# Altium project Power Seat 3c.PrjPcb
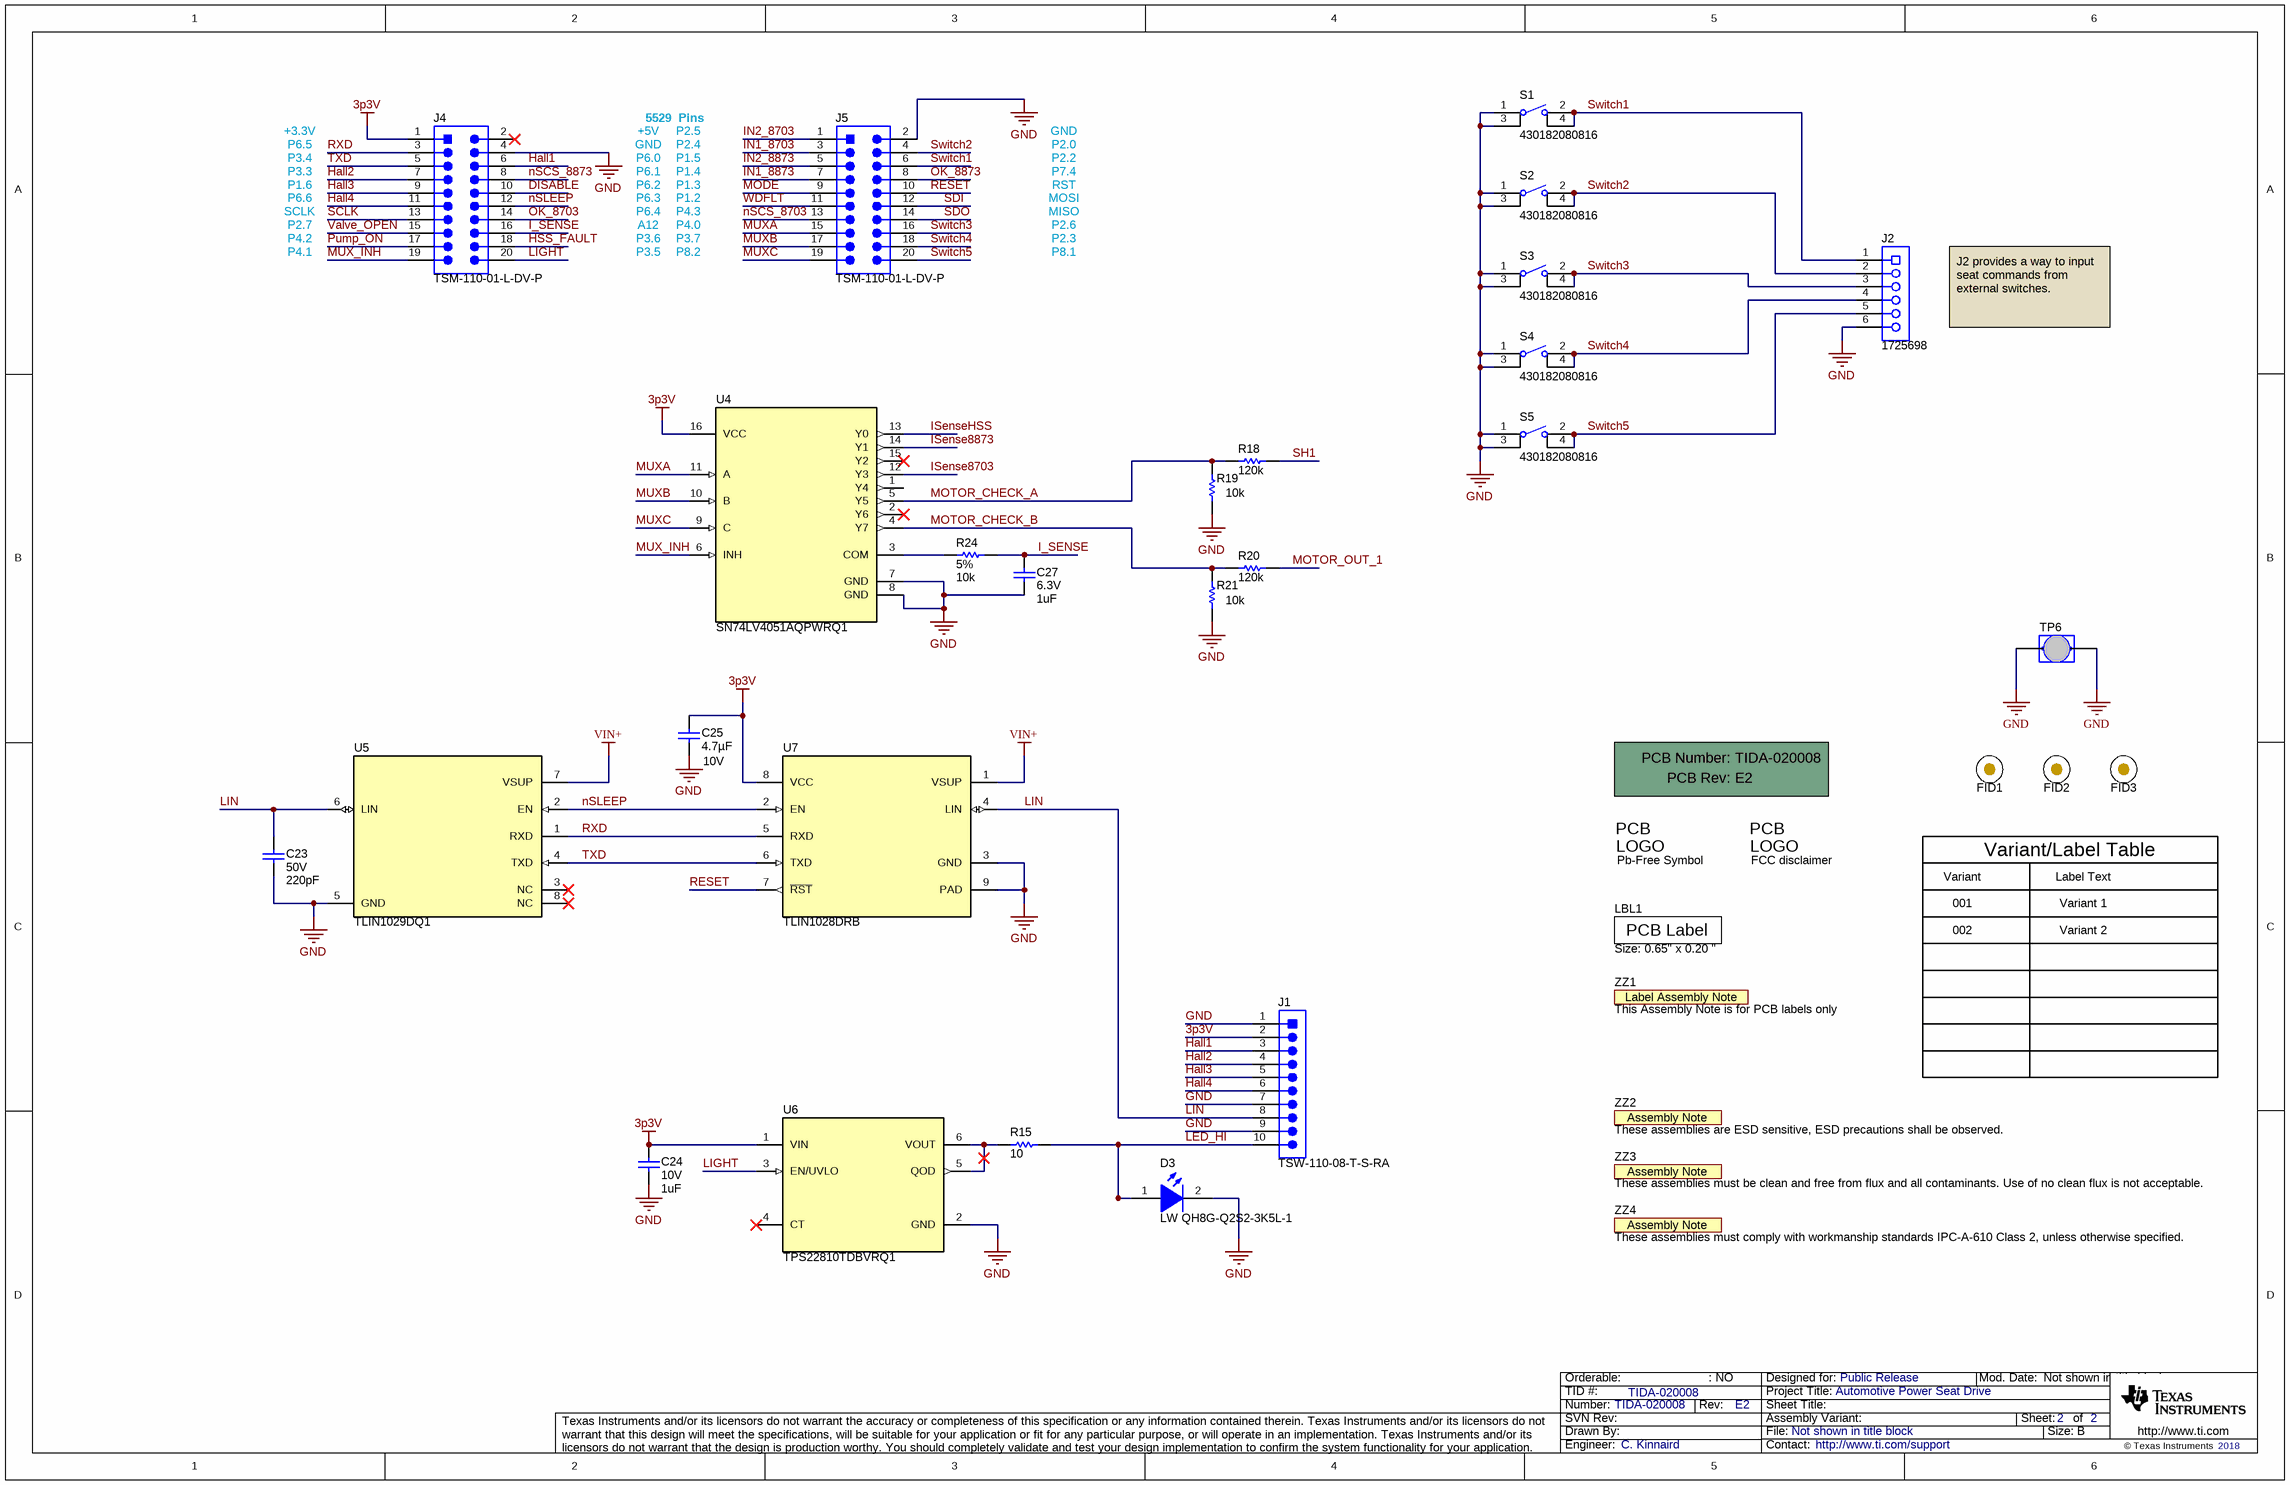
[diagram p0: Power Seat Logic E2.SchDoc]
TID: TIDA-020008; TechSupport: http://www.ti.com/support; SCH_Rev: E2; PRJ_Title: Automotive Power Seat Drive; PRJ_Number: TIDA-020008; PRJ_Engineer: C. Kinnaird; PRJ_Customer: Public Release; PCB_Rev: E2; PCB_Layout: Who did the Layout?; CopyrightYear: 2018
2 sheets, 99 parts. Net scope: global (net labels, ports and power ports of the same name join across sheets).
Board file: Power Seat E2.PcbDoc
Sheets:
  Power Seat Logic E2.SchDoc
  Power Seat Motor Drives E2.SchDoc

## Sheet Power Seat Logic E2.SchDoc
size 431 x 279 mm; Date: Not shown in title block; ApprovedBy: Not shown in title block; CheckedBy: Not shown in title block; Author: Not shown in title block; CompanyName: Not shown in title block; Engineer: Not shown in title block; Organization: Not shown in title block; Address1: Not shown in title block; Address2: Not shown in title block; Address3: Not shown in title block; Address4: Not shown in title block; DocumentNumber: 1; Revision: Use project parameter SCH_Rev; SheetNumber: 2; SheetTotal: 2; PageSetup: Record=PageOptions¦CenterHorizontal=True¦CenterVertical=True¦PrintScale=1.00¦XCorrection=1.00¦YCorrection=1.00¦PrintKind=0¦BorderSize=5000000¦LeftOffset=0¦BottomOffset=0¦Orientation=2¦PaperLength=1000¦PaperWidth=1000¦Scale=100¦PaperSource=15¦PrintQuality=600¦MediaType=1¦DitherType=10¦PaperKind=Letter¦PrintScaleMode=1

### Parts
!PCB1  Printed Circuit Board  (value not drawn)  (mechanical)
C23  VDC_V: 50V  ValueDisplayed: 220pF  [0805_HV]  (hidden comment: C0805C221K5RACTU)
C24  VDC_V: 10V  ValueDisplayed: 1uF  [0603]  (hidden comment: LMK107B7105KAHT)
C25  ValueDisplayed: 4.7µF  Value2: 10V  [0805_HV]  (hidden comment: C2012X7R1A475M125AC)
C27  VDC_V: 6.3V  ValueDisplayed: 1uF  [0402]  (hidden comment: GRM155R70J105MA12D)
D3  LW QH8G-Q2S2-3K5L-1  [LW QH8G_White]
FID1  Fiducial  [Fiducial10-20]  (value not drawn)
FID2  Fiducial  [Fiducial10-20]  (value not drawn)
FID3  Fiducial  [Fiducial10-20]  (value not drawn)
J1  TSW-110-08-T-S-RA  [Samtec_TSW-110-08-x-S-RA]
J2  1725698  [Phoenix_1725698]
J4  TSM-110-01-L-DV-P  [CONN_TSM-110-01-T-DV-P]
J5  TSM-110-01-L-DV-P  [CONN_TSM-110-01-T-DV-P]
LBL1  Size: 0.65" x 0.20 "  [Label_650x200]
Logo2  Pb-Free Symbol  [Pb-Free_Overlay_Small]  (no BOM)
Logo3  FCC disclaimer  [FCC_disclaimer]  (no BOM)
R15  ValueDisplayed: 10  [0603]  (hidden comment: CRCW060310R0JNEAHP)
R18  ValueDisplayed: 120k  [0402]  (hidden comment: CRCW0402120KJNED)
R19  ValueDisplayed: 10k  [0402]  (hidden comment: CRCW040210K0JNED)
R20  ValueDisplayed: 120k  [0402]  (hidden comment: CRCW0402120KJNED)
R21  ValueDisplayed: 10k  [0402]  (hidden comment: CRCW040210K0JNED)
R24  Value1: 5%  ValueDisplayed: 10k  [0402]  (hidden comment: CRCW040210K0JNED)
S1  430182080816  [SW_430182080816]
S2  430182080816  [SW_430182080816]
S3  430182080816  [SW_430182080816]
S4  430182080816  [SW_430182080816]
S5  430182080816  [SW_430182080816]
TP6  D3082-05  [Harwin_D3082-05]  (value not drawn)
U4  SN74LV4051AQPWRQ1  [PW0016A_N]
U5  TLIN1029DQ1  [D0008A_N]
U6  PartNumber: TPS22810TDBVRQ1  [DBV0006A_N]  (hidden comment: TPS22810DBVR)
U7  TLIN1028DRB  [DRB0008F]
ZZ1  This Assembly Note is for PCB labels only  [AssemblyNoteLabel]  (no BOM)
ZZ2  These assemblies are ESD sensitive, ESD precautions shall be observed.  [AssemblyNote]  (no BOM)
ZZ3  These assemblies must be clean and free from flux and all contaminants. Use of no clean flux is not acceptable.  [AssemblyNote]  (no BOM)
ZZ4  These assemblies must comply with workmanship standards IPC-A-610 Class 2, unless otherwise specified.  [AssemblyNote]  (no BOM)

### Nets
3p3V: C24.1 C25.1 J1.2 J4.1 U4.16(VCC) U6.1(VIN) U7.8(VCC)
GND: C23.1 C24.2 C25.2 C27.2 D3.2(K) J1.1 J1.7 J1.9 J2.6 J4.4 J5.2 R19.1 R21.1 S1.1 S1.3 S2.1 S2.3 S3.1 S3.3 S4.1 S4.3 S5.1 S5.3 TP6.1 TP6.2 U4.7(GND) U4.8(GND) U5.5(GND) U6.2(GND) U7.3(GND) U7.9(PAD)
VIN+: U5.7(VSUP) U7.1(VSUP)
DISABLE: J4.10
Hall1: J1.3 J4.6
Hall2: J1.4 J4.7
Hall3: J1.5 J4.9
Hall4: J1.6 J4.11
HSS_FAULT: J4.18
I_SENSE: C27.1 J4.16 R24.1
IN1_8703: J5.3
IN1_8873: J5.7
IN2_8703: J5.1
IN2_8873: J5.5
ISense8703: U4.12(Y3)
ISense8873: U4.14(Y1)
ISenseHSS: U4.13(Y0)
LED_HI: D3.1(A) J1.10 R15.2
LIGHT: J4.20 U6.3(EN/UVLO)
LIN: C23.2 J1.8 U5.6(LIN) U7.4(LIN)
MODE: J5.9
MOTOR_CHECK_A: R18.1 R19.2 U4.5(Y5)
MOTOR_CHECK_B: R20.1 R21.2 U4.4(Y7)
MOTOR_OUT_1: R20.2
MUX_INH: J4.19 U4.6(INH)
MUXA: J5.15 U4.11(A)
MUXB: J5.17 U4.10(B)
MUXC: J5.19 U4.9(C)
nSCS_8703: J5.13
nSCS_8873: J4.8
nSLEEP: J4.12 U5.2(EN) U7.2(EN)
OK_8703: J4.14
OK_8873: J5.8
Pump_ON: J4.17
RESET: J5.10 U7.7(~{RST})
RXD: J4.3 U5.1(RXD) U7.5(RXD)
SCLK: J4.13
SDI: J5.12
SDO: J5.14
SH1: R18.2
Switch1: J2.1 J5.6 S1.2 S1.4
Switch2: J2.2 J5.4 S2.2 S2.4
Switch3: J2.3 J5.16 S3.2 S3.4
Switch4: J2.4 J5.18 S4.2 S4.4
Switch5: J2.5 J5.20 S5.2 S5.4
TXD: J4.5 U5.4(TXD) U7.6(TXD)
Valve_OPEN: J4.15
WDFLT: J5.11
NetR15_1: R15.1 U6.5(QOD) U6.6(VOUT)
NetR24_2: R24.2 U4.3(COM)

Not connected (* = marked no-connect by the designer): J4 2*; U4 1(Y4) 2(Y6)* 15(Y2)*; U5 3(NC)* 8(NC)*; U6 4(CT)*

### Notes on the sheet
- +3.3V
- P6.5
- P3.4
- +5V
- GND
- P6.0
- 5529  Pins
- P2.5
- P2.4
- P1.5
- P2.0
- P2.2
- P3.3
- P1.6
- P6.6
- SCLK
- P2.7
- P6.1
- P6.2
- P6.3
- P6.4
- A12
- P1.4
- P1.3
- P1.2
- P4.3
- P4.0
- P7.4
- RST
- MOSI
- MISO
- P2.6
- P4.2
- P4.1
- P3.6
- P3.5
- P3.7
- P8.2
- P2.3
- P8.1
- J2 provides a way to input seat commands from external switches.
- Variant
- 001
- Variant/Label Table
- Label Text
- Variant 1
- 002
- Variant 2
- : NO

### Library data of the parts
!PCB1 = PCB: Manufacturer: Any; PartNumber: TIDA-020008; SymbolCreator: a0412235
C23 = CMP-0007764-2: CAP, CERM, 220 pF, 50 V, +/- 10%, X7R, 0805; Manufacturer: Kemet; TaMin_C: -55°C; ESR_ohm: 1.414; Polarized: N; SizeAreaWB_mm2: 6.75; Value1: 1.414 ohm; U/M: EA; Value: 220pF; TaMax_C: 125°C; SizeZ_mm: 1.45; SizeX_mm: 2; SizeY_mm: 1.25; Cap_Case: 0805; SizeArea_mm2: 2.5; IRMS_A: 1.11dA; AEC Category: Q200
C24 = CMP-0007505-4: CAP, CERM, 1 uF, 10 V, +/- 10%, X7R, AEC-Q200 Grade 1, 0603; Manufacturer: Taiyo Yuden; TaMin_C: -55°C; Polarized: N; SizeAreaWB_mm2: 4.68; Value1: Unknown; U/M: EA; Value: 1uF; TaMax_C: 125°C; SizeZ_mm: 1; SizeX_mm: 1.6; SizeY_mm: 0.8; SizeArea_mm2: 1.28; AEC Qualified: Y; Cap_F: 1µF; AEC Category: Q200
C25 = C2012X7R1A475M125AC: CAP, CERM, 4.7 µF, 10 V,+/- 20%, X7R, 0805; Manufacturer: TDK; Polarized: N; CompType: Capacitor; Value: 4.7uF; U/M: EA; Cap_F: 0.0000047; Tolerance_%: 20; VDC_V: 10; TaMin_C: -55; TaMax_C: 125; Cap_Case: 0805; SizeArea_mm2: 2.5; SizeAreaWB_mm2: 6.75; SizeX_mm: 2; SizeY_mm: 1.25; SizeZ_mm: 1.45; AEC Category: Q200; Green_Lifecycle: Active; Green_REACh: Passed
C27 = CMP-0006624-2: CAP, CERM, 1 uF, 6.3 V, +/- 20%, X7R, 0402; Manufacturer: MuRata; TaMin_C: -55°C; Polarized: N; SizeAreaWB_mm2: 3; Value1: Unknown; U/M: EA; Value: 1uF; TaMax_C: 125°C; SizeZ_mm: 0.6; SizeX_mm: 1; SizeY_mm: 0.5; CompType: Capacitor; Cap_F: 1µF; AEC Category: Q200
D3 = CMP-0002919-1: LED, White, SMD; Manufacturer: OSRAM; Io_A: 5mA; Vr_V: 5V; Tjmax_C: 95°C; Value1: W; U/M: EA; Angle: 120; Ir_A: 10nA; Vf_V: 2.8V
FID1-FID3 = Fiducial: Fiducial mark.  There is nothing to buy or mount.; SymbolCreator: codlsc
J1 = CMP-0075666-1: Header, 2.54mm, 10x1, Tin, R/A, TH; Manufacturer: Samtec; Pitch_mm: 2.54; Gender: Male; Cert_CSA: Y; Voltage_V: 550V; CT: False; Shrouded: N; Row_Count: 1; CNHeader: True
J2 = CMP-0055512-1: Terminal Block, 6x1, 2.54mm, TH; Manufacturer: Phoenix Contact; CNHeader: FALSE; Current_A: 6A; Cert_CSA: Y; Voltage_V: 160V; Row_Count: 1; Pitch_mm: 2.54; CT: TRUE
J4 J5 = CMP-0075600-2: Header, 2.54mm, 10x2, Gold, SMT; Manufacturer: Samtec; Pitch_mm: 2.54; Gender: Male; Cert_CSA: Y; Green_REACh: Passed; Current_A: 5.4A; Voltage_V: 475V; Shrouded: N; Green_Lifecycle: Active; Row_Count: 2
LBL1 = THT-14-423-10: Thermal Transfer Printable Labels, 0.650" W x 0.200" H - 10,000 per roll; Manufacturer: Brady; SymbolCreator: a0412235; CompType: Label
Logo2 = Pb-Free: SymbolCreator: a0412235
Logo3 = FCC_disclaimer: SymbolCreator: codlsc
R15 = CMP-0025704-4: RES, 10, 5%, 0.25 W, AEC-Q200 Grade 0, 0603; Manufacturer: Vishay-Dale; Power_W: 250mW; TempCo: 200 ppm/C; Value_Code: 10R0; Value: 10; EIA_Code: E24; SizeX_mm: 1.6; SizeY_mm: 0.8; SizeZ_mm: 1; Value2: 0.25W; SizeArea_mm2: 1.28; AEC Qualified: Y; VDC_V: 75V; AEC Category: Q200; AEC Grade: 0
R18 R20 = CMP-0026832-2: RES, 120 k, 5%, 0.063 W, AEC-Q200 Grade 0, 0402; Manufacturer: Vishay-Dale; Power_W: 63mW; TempCo: 200 ppm/C; Value: 120k; EIA_Code: E24; SizeX_mm: 1; SizeY_mm: 0.5; SizeZ_mm: 0.6; Value2: 0.063W; AEC Qualified: Y; VDC_V: 50V; AEC Category: Q200; AEC Grade: 0
R19 R21 R24 = CMP-0026825-5: RES, 10 k, 5%, 0.063 W, AEC-Q200 Grade 0, 0402; Manufacturer: Vishay-Dale; Power_W: 63mW; TempCo: 200 ppm/C; Value_Code: 10k0; Value: 10k; EIA_Code: E24; SizeX_mm: 1; SizeY_mm: 0.5; SizeZ_mm: 0.6; Value2: 0.063W; CompType: Resistor; AEC Qualified: Y; VDC_V: 50V; AEC Category: Q200; AEC Grade: 0
S1-S5 = CMP-0002215-1: Switch, Tactile, SPST-NO, 0.05A, 12V, SMD; Manufacturer: Wurth Elektronik; CurrentRating_mA: 50A; SwitchFunction: Off-Mom; PositionCount: 1
TP6 = D3082-05: 1mm Uninsulated Shorting Plug, 10.16mm spacing, TH; Manufacturer: Harwin; SymbolCreator: a0799628; CompType: Jumper Wire
U4 = SN74LV4051AQPWRQ1: Automotive Catalog 8-Channel Analog Multiplexer/Demultiplexer, PW0016A (TSSOP-16); Manufacturer: Texas Instruments; SymbolCreator: Altium; SizeArea_mm2: 32; SizeAreaWB_mm2: 58.8; SizeX_mm: 6.4; SizeY_mm: 5; SizeZ_mm: 1.2; CompType: IC; U/M: EA
U5 = CMP-0079114-1: Local Interconnect Network (LIN) Transceiver with Dominant State Timeout, D0008A (SOIC-8); Alternate PartNumber: TLIN1029DRQ1; Alternate Manufacturer: Texas Instruments; SizeAreaWB_mm2: 56.58; SizeZ_mm: 1.75; SizeX_mm: 4.9; SizeY_mm: 6.2; SizeArea_mm2: 30.38; CompType: IC; AEC Qualified: Y; AEC Category: Q200
U6 = CMP-0073661-1: 2.7-18-V, 2-A, 79-mΩ On-Resistance Load Switch with Thermal Protection, DBV0006A (SOT-23-6); Alternate PartNumber: TPS22810DBVT; Alternate Manufacturer: Texas Instruments; Green_Lifecycle: Active; SizeAreaWB_mm2: 14.82; Green_REACh: Passed; U/M: EA; SizeZ_mm: 1.45; SizeX_mm: 2.8; SizeY_mm: 2.9; SizeArea_mm2: 8.12; CompType: IC
U7 = CMP-0074650-2: Automotive Local Interconnect Network Transceiver, DRB0008F (VSON-8); Manufacturer: Texas Instruments; SizeX_mm: 3.0; CompType: IC; SizeZ_mm: 1.0; SizeArea_mm2: 9.0; SizeAreaWB_mm2: 16.0; U/M: EA
ZZ1 = AssemblyNoteLabel: SymbolCreator: a0412235
ZZ2-ZZ4 = AssemblyNote: SymbolCreator: codlsc

## Sheet Power Seat Motor Drives E2.SchDoc
size 431 x 279 mm; Date: Not shown in title block; ApprovedBy: Not shown in title block; CheckedBy: Not shown in title block; Author: Not shown in title block; CompanyName: Not shown in title block; DrawnBy: C. Kinnaird; Engineer: Not shown in title block; Organization: Not shown in title block; Address1: Not shown in title block; Address2: Not shown in title block; Address3: Not shown in title block; Address4: Not shown in title block; DocumentNumber: 1; Revision: Use project parameter SCH_Rev; SheetNumber: 1; SheetTotal: 2; PageSetup: Record=PageOptions¦CenterHorizontal=True¦CenterVertical=True¦PrintScale=1.00¦XCorrection=1.00¦YCorrection=1.00¦PrintKind=0¦BorderSize=5000000¦LeftOffset=0¦BottomOffset=0¦Orientation=2¦PaperLength=1000¦PaperWidth=1000¦Scale=100¦PaperSource=15¦PrintQuality=600¦MediaType=1¦DitherType=10¦PaperKind=Letter¦PrintScaleMode=1
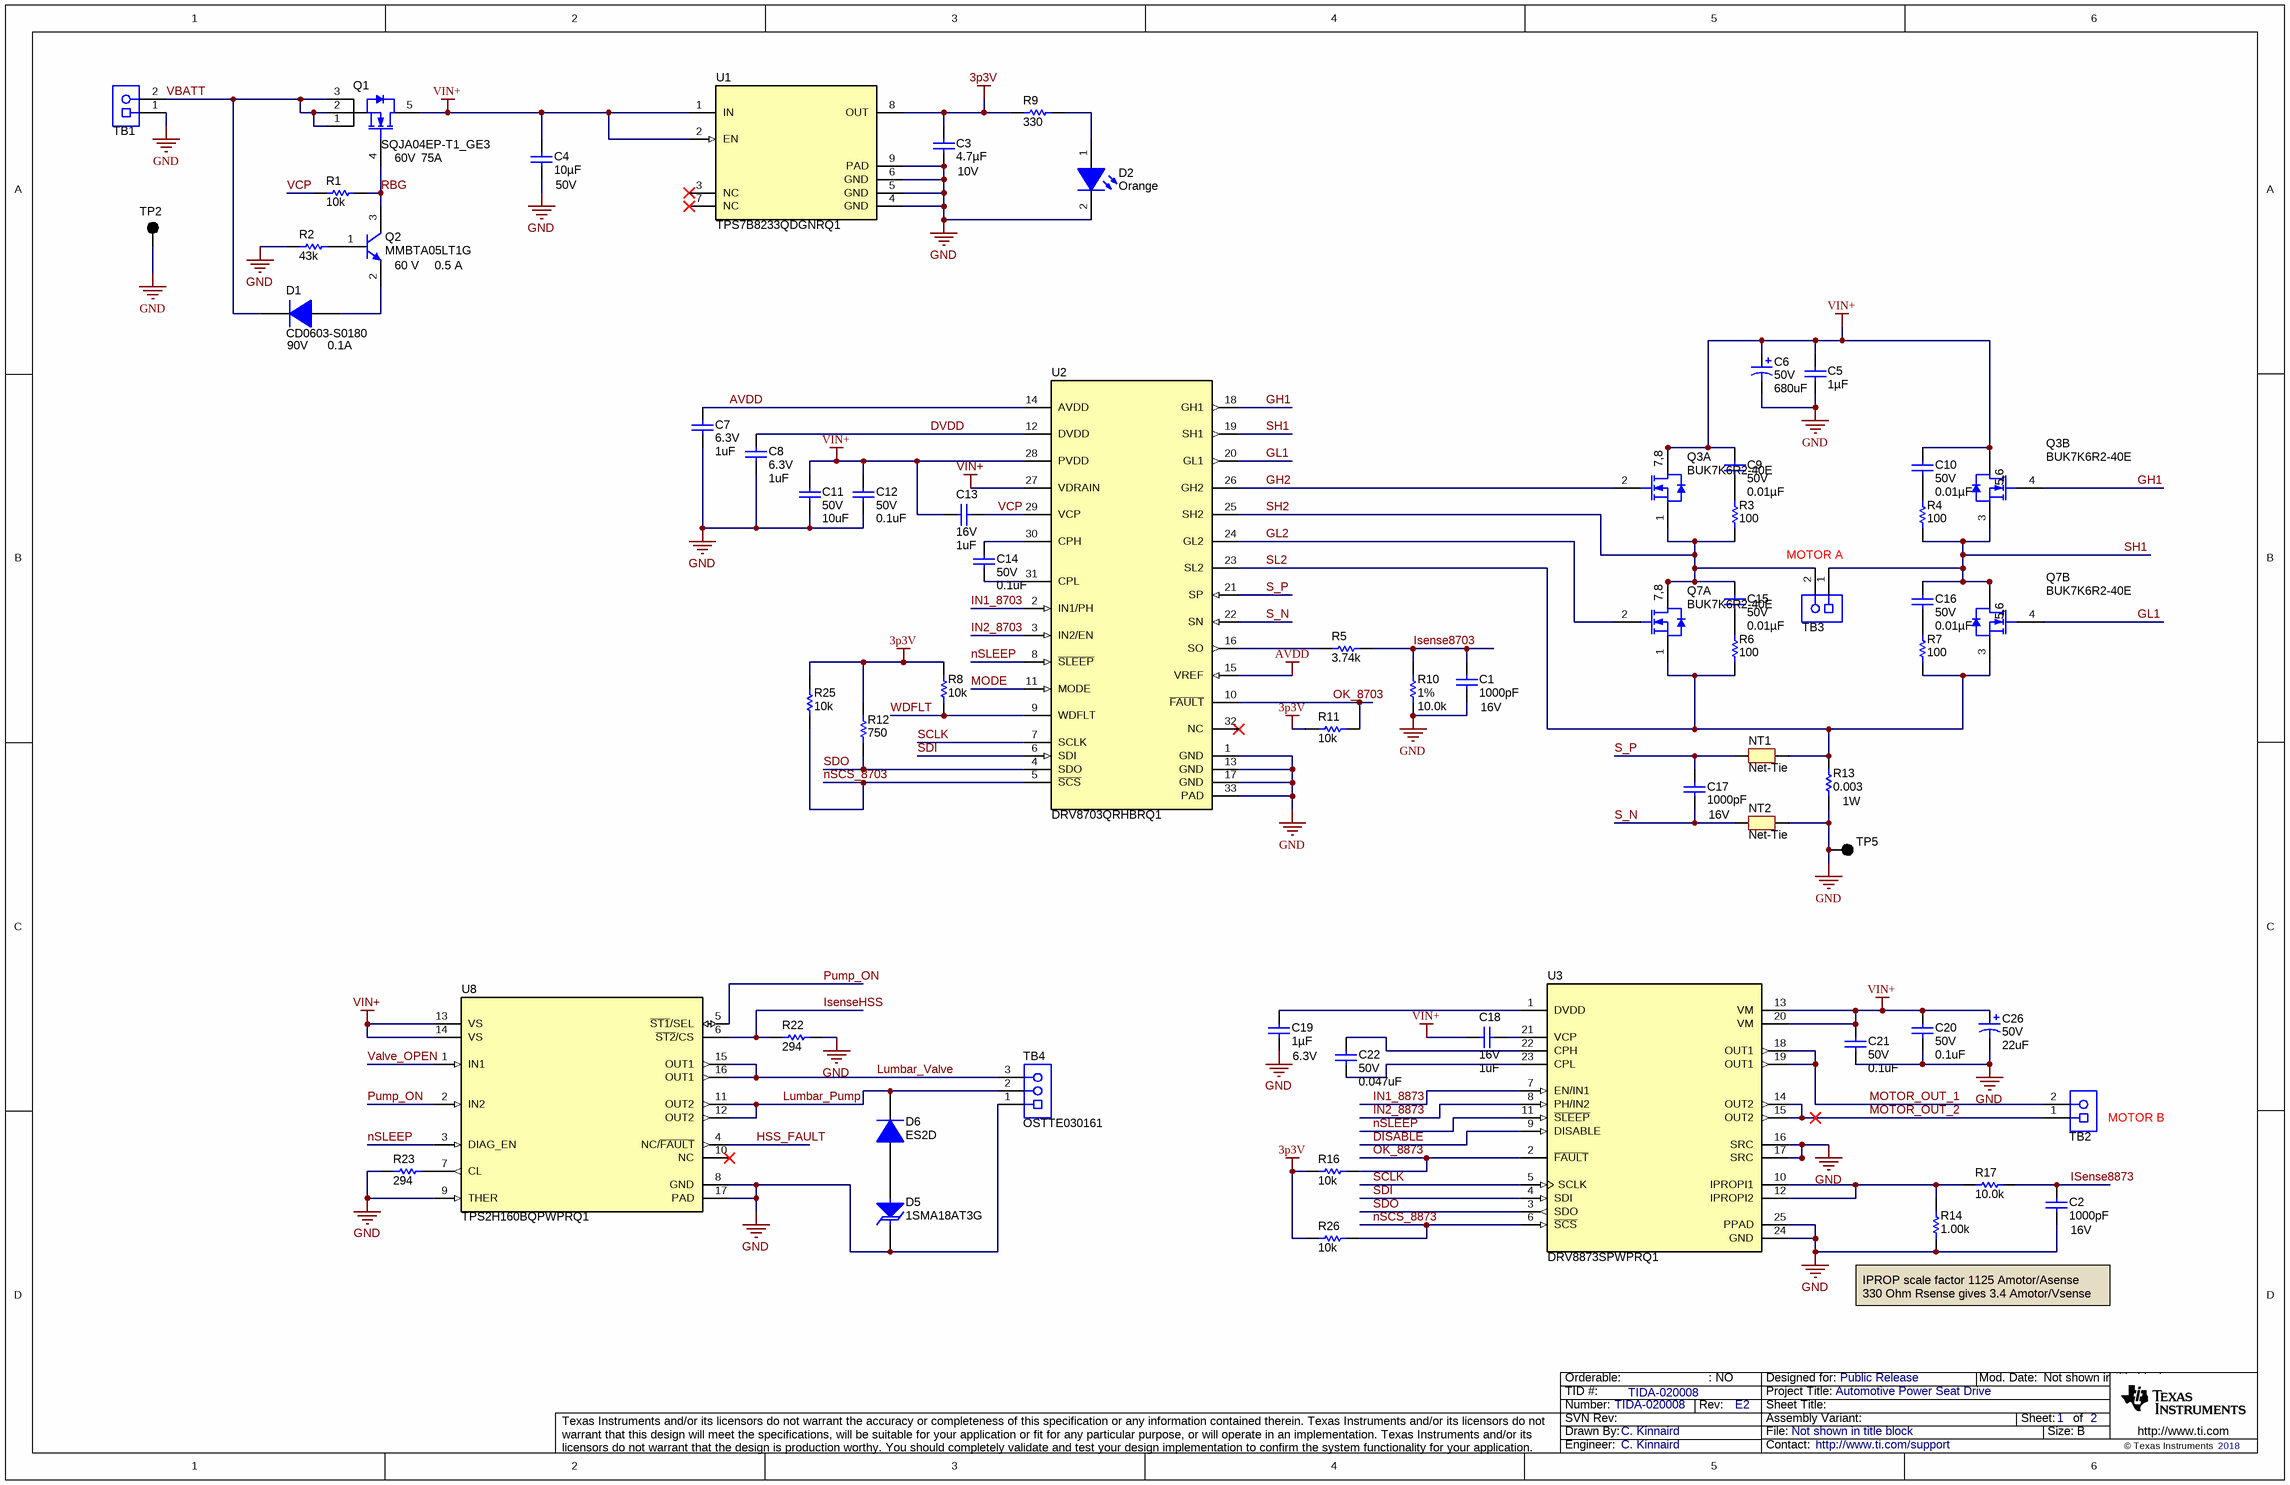
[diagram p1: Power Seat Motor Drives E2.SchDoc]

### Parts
C1  ValueDisplayed: 1000pF  Value2: 16V  [0402L]  (hidden comment: GRM155R71C102KA01D)
C2  ValueDisplayed: 1000pF  Value2: 16V  [0402L]  (hidden comment: GRM155R71C102KA01D)
C3  ValueDisplayed: 4.7µF  Value2: 10V  [0805_HV]  (hidden comment: C2012X7R1A475M125AC)
C4  ValueDisplayed: 10µF  Value2: 50V  [1210_280]  (hidden comment: UMK325AB7106KMHT)
C5  ValueDisplayed: 1µF  [0805L]  (hidden comment: GRM21BR71H105KA12L)
C6  VDC_V: 50V  ValueDisplayed: 680uF  [SM_RADIAL_J16]  (hidden comment: EEV-FK1H681M)
C7  VDC_V: 6.3V  ValueDisplayed: 1uF  [0402]  (hidden comment: GRM155R70J105MA12D)
C8  VDC_V: 6.3V  ValueDisplayed: 1uF  [0402]  (hidden comment: GRM155R70J105MA12D)
C9  VDC_V: 50V  ValueDisplayed: 0.01µF  [0402]  (hidden comment: CGA2B3X8R1H103K050BB)
C10  VDC_V: 50V  ValueDisplayed: 0.01µF  [0402]  (hidden comment: CGA2B3X8R1H103K050BB)
C11  VDC_V: 50V  ValueDisplayed: 10uF  [1206_180]  (hidden comment: CL31B106KBHNNNE)
C12  VDC_V: 50V  ValueDisplayed: 0.1uF  [0603]  (hidden comment: C1608X7R1H104K080AA)
C13  VDC_V: 16V  ValueDisplayed: 1uF  [0603]  (hidden comment: C1608X7R1C105K080AC)
C14  VDC_V: 50V  ValueDisplayed: 0.1uF  [0603]  (hidden comment: C1608X7R1H104K080AA)
C15  VDC_V: 50V  ValueDisplayed: 0.01µF  [0402]  (hidden comment: CGA2B3X8R1H103K050BB)
C16  VDC_V: 50V  ValueDisplayed: 0.01µF  [0402]  (hidden comment: CGA2B3X8R1H103K050BB)
C17  ValueDisplayed: 1000pF  Value2: 16V  [0402L]  (hidden comment: GRM155R71C102KA01D)
C18  VDC_V: 16V  ValueDisplayed: 1uF  [0603]  (hidden comment: EMK107B7105KA-T)
C19  ValueDisplayed: 1µF  Value2: 6.3V  [0603L]  (hidden comment: GRM188R70J105KA01D)
C20  VDC_V: 50V  ValueDisplayed: 0.1uF  [0402]  (hidden comment: CGA2B3X7R1H104M050BB)
C21  VDC_V: 50V  ValueDisplayed: 0.1uF  [0402]  (hidden comment: CGA2B3X7R1H104M050BB)
C22  VDC_V: 50V  ValueDisplayed: 0.047uF  [0402]  (hidden comment: CGA2B3X7R1H473K050BB)
C26  VDC_V: 50V  ValueDisplayed: 22uF  [Panasonic_500x1100]  (hidden comment: ECA1HM220)
D1  CD0603-S0180  value 90V  Value1: 0.1A  [Diode_0603]
D2  value Orange  [LTST-C191_Orange]  (hidden comment: LTST-C191KFKT)
D5  1SMA18AT3G  [SMA]
D6  ES2D  [SMB]
NT1  Net-Tie  [Net-Tie_10mil]  (net tie, no BOM)
NT2  Net-Tie  [Net-Tie_10mil]  (net tie, no BOM)
Q1  SQJA04EP-T1_GE3  value 60V  IdsMax_A: 75A  [PowerPAK_SO-8L]
Q2  MMBTA05LT1G  value 60 V  Value1: 0.5 A  [SOT-23]
Q3  BUK7K6R2-40E  [SOT1205]  (parts A,B of 2)
Q7  BUK7K6R2-40E  [SOT1205]  (parts A,B of 2)
R1  ValueDisplayed: 10k  [0402]  (hidden comment: CRCW040210K0JNED)
R2  ValueDisplayed: 43k  [0402]  (hidden comment: CRCW040243K0JNED)
R3  ValueDisplayed: 100  [0402]  (hidden comment: CRCW0402100RFKED)
R4  ValueDisplayed: 100  [0402]  (hidden comment: CRCW0402100RFKED)
R5  ValueDisplayed: 3.74k  [0402]  (hidden comment: CRCW04023K74FKED)
R6  ValueDisplayed: 100  [0402]  (hidden comment: CRCW0402100RFKED)
R7  ValueDisplayed: 100  [0402]  (hidden comment: CRCW0402100RFKED)
R8  value 10k  [0603L]  (hidden comment: CRCW060310K0JNEA)
R9  ValueDisplayed: 330  [0603]  (hidden comment: CRCW0603330RJNEA)
R10  Value1: 1%  ValueDisplayed: 10.0k  [0402]  (hidden comment: RC0402FR-0710KL)
R11  value 10k  [0603L]  (hidden comment: CRCW060310K0JNEA)
R12  ValueDisplayed: 750  [0603L]  (hidden comment: RC0603JR-07750RL)
R13  Value2: 1W  ValueDisplayed: 0.003  [1206]  (hidden comment: CSNL1206FT3L00)
R14  ValueDisplayed: 1.00k  [0603]  (hidden comment: CRCW06031K00FKEA)
R16  value 10k  [0603L]  (hidden comment: CRCW060310K0JNEA)
R17  ValueDisplayed: 10.0k  [0603]  (hidden comment: CRCW060310K0FKEA)
R22  ValueDisplayed: 294  [0402]  (hidden comment: CRCW0402294RFKED)
R23  ValueDisplayed: 294  [0402]  (hidden comment: CRCW0402294RFKED)
R25  value 10k  [0603L]  (hidden comment: CRCW060310K0JNEA)
R26  value 10k  [0603L]  (hidden comment: CRCW060310K0JNEA)
TB1  1715721  [PhoenixContact_1715721]  (value not drawn)
TB2  1715721  [PhoenixContact_1715721]  (value not drawn)
TB3  1715721  [PhoenixContact_1715721]  (value not drawn)
TB4  OSTTE030161  [On-Shore_OSTTE030161]
TP2  5006  [Keystone5006]  (value not drawn)
TP5  5006  [Keystone5006]  (value not drawn)
U1  TPS7B8233QDGNRQ1  [DGN0008D_N]
U2  DRV8703QRHBRQ1  [RHB0032E]
U3  DRV8873SPWPRQ1  [PWP0024J_M]
U8  TPS2H160BQPWPRQ1  [PWP0016J_N]

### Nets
3p3V: C3.1 R8.2 R9.1 R11.1 R12.2 R16.1 R25.2 R26.1 U1.8(OUT)
AVDD: C7.1 U2.14(AVDD) U2.15(VREF)
GND: C1.2 C2.2 C3.2 C4.2 C5.2 C6.2(-) C7.2 C8.2 C11.2 C12.2 C19.1 C20.2 C21.2 C26.2(-) D2.2(K) D5.1(K) NT2.2 R2.1 R10.1 R13.1 R14.1 R22.2 R23.1 TB1.1 TB4.1 TP2.1 TP5.1 U1.4(GND) U1.5(GND) U1.6(GND) U1.9(PAD) U2.1(GND) U2.13(GND) U2.17(GND) U2.33(PAD) U3.16(SRC) U3.17(SRC) U3.24(GND) U3.25(PPAD) U8.8(GND) U8.9(THER) U8.17(PAD)
VIN+: C4.1 C5.1 C6.1(+) C9.1 C10.1 C11.1 C12.1 C13.2 C18.2 C20.1 C21.1 C26.1(+) Q1.5(D) Q3.5(D) Q3.6(D) Q3.7(D) Q3.8(D) U1.1(IN) U1.2(EN) U2.27(VDRAIN) U2.28(PVDD) U3.13(VM) U3.20(VM) U8.13(VS) U8.14(VS)
DISABLE: U3.9(DISABLE)
DVDD: C8.1 U2.12(DVDD)
GH1: Q3.4(G) U2.18(GH1)
GH2: Q3.2(G) U2.26(GH2)
GL1: Q7.4(G) U2.20(GL1)
GL2: Q7.2(G) U2.24(GL2)
HSS_FAULT: U8.4(NC/~{FAULT})
IN1_8703: U2.2(IN1/PH)
IN1_8873: U3.7(EN/IN1)
IN2_8703: U2.3(IN2/EN)
IN2_8873: U3.8(PH/IN2)
ISense8703: C1.1 R5.2 R10.2
ISense8873: C2.1 R17.1
ISenseHSS: R22.1 U8.6(~{ST2}/CS)
Lumbar_Pump: D6.1(K) TB4.2 U8.11(OUT2) U8.12(OUT2)
Lumbar_Valve: TB4.3 U8.15(OUT1) U8.16(OUT1)
MODE: U2.11(MODE)
MOTOR_OUT_1: TB2.2 U3.18(OUT1) U3.19(OUT1)
MOTOR_OUT_2: TB2.1 U3.14(OUT2) U3.15(OUT2)
nSCS_8703: R25.1 U2.5(~{SCS})
nSCS_8873: R26.2 U3.6(~{SCS})
nSLEEP: U2.8(~{SLEEP}) U3.11(~{SLEEP}) U8.3(DIAG_EN)
OK_8703: R11.2 U2.10(~{FAULT})
OK_8873: R16.2 U3.2(~{FAULT})
Pump_ON: U8.2(IN2) U8.5(~{ST1}/SEL)
RBG: Q1.4(G) Q2.3(C) R1.1
S_N: C17.2 NT2.1 U2.22(SN)
S_P: C17.1 NT1.2 U2.21(SP)
SCLK: U2.7(SCLK) U3.5(SCLK)
SDI: U2.6(SDI) U3.4(SDI)
SDO: R12.1 U2.4(SDO) U3.3(SDO)
SH1: C16.1 Q3.3(S) Q7.5(D) Q7.6(D) R4.1 TB3.1 U2.19(SH1)
SH2: C15.1 Q3.1(S) Q7.7(D) Q7.8(D) R3.1 TB3.2 U2.25(SH2)
SL2: NT1.1 Q7.1(S) Q7.3(S) R6.1 R7.1 R13.2 U2.23(SL2)
Valve_OPEN: U8.1(IN1)
VBATT: D1.1(K) Q1.1(S) Q1.2(S) Q1.3(S) TB1.2
VCP: C13.1 R1.2 U2.29(VCP)
WDFLT: R8.1 U2.9(WDFLT)
NetC9_2: C9.2 R3.2
NetC10_2: C10.2 R4.2
NetC14_1: C14.1 U2.30(CPH)
NetC14_2: C14.2 U2.31(CPL)
NetC15_2: C15.2 R6.2
NetC16_2: C16.2 R7.2
NetC18_1: C18.1 U3.21(VCP)
NetC19_2: C19.2 U3.1(DVDD)
NetC22_1: C22.1 U3.22(CPH)
NetC22_2: C22.2 U3.23(CPL)
NetD1_2: D1.2(A) Q2.2(E)
NetD2_1: D2.1(A) R9.2
NetD5_2: D5.2(A) D6.2(A)
NetQ2_1: Q2.1(B) R2.2
NetR5_1: R5.1 U2.16(SO)
NetR14_2: R14.2 R17.2 U3.10(IPROPI1) U3.12(IPROPI2)
NetR23_2: R23.2 U8.7(CL)

Not connected (* = marked no-connect by the designer): U1 3(NC)* 7(NC)*; U2 32(NC)*; U8 10(NC)*

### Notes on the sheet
- (near TB3) MOTOR A
- (near TB2) MOTOR B
- (near R14) IPROP scale factor 1125 Amotor/Asense
  330 Ohm Rsense gives 3.4 Amotor/Vsense
- : NO

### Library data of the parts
C1 C2 C17 = GRM155R71C102KA01D: CAP, CERM, 1000 pF, 16 V, +/- 10%, X7R, 0402; Manufacturer: MuRata; Polarized: N; CompType: Capacitor; Value: 1000pF; U/M: EA; Cap_F: 0.000000001; Tolerance_%: 10; Value1: Unknown; VDC_V: 16; TaMin_C: -55; TaMax_C: 125; Cap_Case: 0402; AEC Category: Q200
C3 = C2012X7R1A475M125AC: as C25 on sheet Power Seat Logic E2
C4 = UMK325AB7106KMHT: CAP, CERM, 10 µF, 50 V,+/- 10%, X7R, AEC-Q200 Grade 1, 1210; Manufacturer: Taiyo Yuden; Polarized: N; CompType: Capacitor; Value: 10uF; U/M: EA; Cap_F: 0.00001; Tolerance_%: 10; VDC_V: 50; TaMin_C: -55; TaMax_C: 125; Cap_Case: 1210; SizeArea_mm2: 8; SizeAreaWB_mm2: 14.7; SizeX_mm: 3.2; SizeY_mm: 2.5; SizeZ_mm: 2.8; AEC Category: Q200; AEC Qualified: Y; AEC Grade: 1
C5 = GRM21BR71H105KA12L: CAP, CERM, 1 µF, 50 V, +/- 10%, X7R, 0805; Manufacturer: MuRata; Polarized: N; CompType: Capacitor; Value: 1uF; U/M: EA; Cap_F: 0.000001; Tolerance_%: 10; Value1: Unknown; VDC_V: 50; Value2: 50V; TaMin_C: -55; TaMax_C: 125; Cap_Case: 0805; AEC Category: Q200
C6 = CMP-0011212-2: CAP, AL, 680 uF, 50 V, +/- 20%, 0.073 ohm, AEC-Q200 Grade 2, SMD; Manufacturer: Panasonic; TaMin_C: -55°C; ESR_ohm: 0.073; Polarized: Y; SizeAreaWB_mm2: 399; U/M: EA; Value: 680uF; TaMax_C: 105°C; SizeZ_mm: 16.5; SizeX_mm: 19; SizeY_mm: 17; Cap_Case: J16; SizeArea_mm2: 323; CompType: Capacitor; Cap_F: 680µF; IRMS_A: 1.61A; AEC Grade: 2; AEC Category: Q200
C7 C8 = CMP-0006624-2: as C27 on sheet Power Seat Logic E2
C9 C10 C15 C16 = CMP-0078224-1: CAP, CERM, 0.01 µF, 50 V,+/- 10%, X8R, AEC-Q200 Grade 0, 0402; Manufacturer: TDK; TaMin_C: -55°C; Polarized: N; SizeAreaWB_mm2: 3; U/M: EA; Value: 0.01uF; TaMax_C: 150°C; SizeZ_mm: 0.6; SizeX_mm: 1; SizeY_mm: 0.5; CompType: Capacitor; AEC Qualified: Y; Cap_F: 10nF; AEC Grade: 0; AEC Category: Q200
C11 = CMP-0008802-2: CAP, CERM, 10 uF, 50 V, +/- 10%, X7R, 1206; Manufacturer: Samsung; TaMin_C: -55°C; Polarized: N; SizeAreaWB_mm2: 10.92; Value1: Unknown; U/M: EA; Value: 10uF; TaMax_C: 125°C; SizeZ_mm: 1.8; SizeX_mm: 3.2; SizeY_mm: 1.6; Cap_Case: 1206; SizeArea_mm2: 5.12; CompType: Capacitor; Cap_F: 10µF; AEC Category: Q200
C12 C14 = CMP-0007044-5: CAP, CERM, 0.1 uF, 50 V, +/- 10%, X7R, 0603; Manufacturer: TDK; TaMin_C: -55°C; ESR_ohm: 0.0296; Polarized: N; SizeAreaWB_mm2: 4.68; Value1: 0.0296 ohm; U/M: EA; Value: 0.1uF; TaMax_C: 125°C; SizeZ_mm: 1; SizeX_mm: 1.6; SizeY_mm: 0.8; SizeArea_mm2: 1.28; CompType: Capacitor; Cap_F: 100nF; IRMS_A: 9.7199dA; AEC Category: Q200
C13 = CMP-0007037-4: CAP, CERM, 1 uF, 16 V, +/- 10%, X7R, 0603; Manufacturer: TDK; TaMin_C: -55°C; ESR_ohm: 5.7m; Polarized: N; SizeAreaWB_mm2: 4.68; Value1: 0.0057 ohm; U/M: EA; Value: 1uF; TaMax_C: 125°C; SizeZ_mm: 1; SizeX_mm: 1.6; SizeY_mm: 0.8; SizeArea_mm2: 1.28; CompType: Capacitor; Cap_F: 1µF; AEC Category: Q200
C18 = CMP-0007120-4: CAP, CERM, 1 uF, 16 V, +/- 10%, X7R, 0603; Manufacturer: Taiyo Yuden; TaMin_C: -55°C; Polarized: N; SizeAreaWB_mm2: 4.68; Value1: Unknown; U/M: EA; Value: 1uF; TaMax_C: 85°C; SizeZ_mm: 1; SizeX_mm: 1.6; SizeY_mm: 0.8; SizeArea_mm2: 1.28; Cap_F: 1µF; AEC Category: Q200
C19 = GRM188R70J105KA01D: CAP, CERM, 1 µF, 6.3 V, +/- 10%, X7R, 0603; Manufacturer: MuRata; Polarized: N; CompType: Capacitor; Value: 1uF; U/M: EA; Cap_F: 0.000001; Tolerance_%: 10; Value1: Unknown; VDC_V: 6.3; TaMin_C: -55; TaMax_C: 125; Cap_Case: 0603; AEC Category: Q200
C20 C21 = CMP-0006326-2: CAP, CERM, 0.1 uF, 50 V, +/- 20%, X7R, AEC-Q200 Grade 1, 0402; Manufacturer: TDK; TaMin_C: -55°C; Polarized: N; SizeAreaWB_mm2: 3; Value1: Unknown; U/M: EA; Value: 0.1uF; TaMax_C: 125°C; SizeZ_mm: 0.6; SizeX_mm: 1; SizeY_mm: 0.5; AEC Qualified: Y; Cap_F: 100nF; AEC Category: Q200
C22 = CMP-0006330-2: CAP, CERM, 0.047 uF, 50 V, +/- 10%, X7R, AEC-Q200 Grade 1, 0402; Manufacturer: TDK; TaMin_C: -55°C; ESR_ohm: 0.06407; Polarized: N; SizeAreaWB_mm2: 3; Value1: 0.06407 ohm; U/M: EA; TaMax_C: 125°C; SizeZ_mm: 0.6; SizeX_mm: 1; SizeY_mm: 0.5; CompType: Capacitor; AEC Qualified: Y; Cap_F: 47nF; IRMS_A: 6.46122dA; AEC Category: Q200
C26 = CMP-0064895-2: CAP, AL, 22 uF, 50 V, +/- 20%, TH; Manufacturer: Panasonic; TaMin_C: -40°C; Polarized: Y; SizeAreaWB_mm2: 49; Value1: Unknown; U/M: EA; Value: 22uF; TaMax_C: 85°C; SizeZ_mm: 12.5; SizeX_mm: 5; Cap_Case: 5x11; SizeArea_mm2: 25; CompType: Capacitor; AEC Qualified: N; Cap_F: 22µF; AEC Category: Q200
D1 = CMP-0029009-1: Diode, Switching, 90 V, 0.1 A, 0603 Diode; Manufacturer: Bourns; Io_A: 1dA; Green_Lifecycle: Not Set; SizeAreaWB_mm2: 5.13; Green_REACh: Incomplete; TJmax_C: 125°C; U/M: EA; SizeZ_mm: 0.75; SizeX_mm: 1.7; SizeY_mm: 0.9; Vf_V: 1V; SizeArea_mm2: 1.53; AEC Category: Q101
D2 = LTST-C191KFKT: LED, Orange, SMD; Manufacturer: Lite-On; Type: AlInGaP; Vf_V: 2; Value2: 2V; Io_A: 0.02; Vr_V: 5; Ir_A: 1e-005; Tjmax_C: 85; Power_TotalModule: 0.075; Value1: 0.075W; Angle: 130; U/M: EA; Green_Lifecycle: Not Set; Green_REACh: Incomplete
D5 = CMP-0005446-2: Diode, TVS, Uni, 18 V, 29.2 Vc, AEC-Q101, SMA; Manufacturer: Littelfuse; Power_W: 1.5W; SizeAreaWB_mm2: 37.3428; Vr_V: 18V; RJA_CperW: 250; U/M: EA; Value: 18V; SizeZ_mm: 2.87; SizeX_mm: 5.59; SizeY_mm: 2.92; SizeArea_mm2: 16.3228; AEC Qualified: Y; AEC Category: Q101
D6 = CMP-0029161-1: Diode, Fast Rectifier, 200 V, 2 A, SMB; Manufacturer: Fairchild Semiconductor; Io_A: 2A; Green_Lifecycle: Not Set; SizeAreaWB_mm2: 44.156; Vr_V: 200V; Green_REACh: Incomplete; TJmax_C: 150°C; U/M: EA; Value: 200V; SizeZ_mm: 2.6; SizeX_mm: 5.6; SizeY_mm: 3.81; Vf_V: 9dV; Value2: 0.9V; SizeArea_mm2: 21.336; AEC Qualified: N; AEC Category: Q101
NT1 NT2 = Net-Tie: Single point connection between nets.; SymbolCreator: codlsc
Q1 = CMP-0077286-1: MOSFET, N-CH, 60 V, 75 A, AEC-Q101, PowerPAK_SO-8L; Manufacturer: Vishay-Siliconix; Alternate Manufacturer: None; ChType: N; QgTyp_nC: 35.0; SizeAreaWB_mm2: 58.1095; SizeArea_mm2: 31.5495; AEC Qualified: Y; Vgs_V: 20V; AEC Category: Q101; SizeZ_mm: 1.14; SizeY_mm: 5.13; Value2: 35 nC; U/M: EA; Value1: ? ohm; SizeX_mm: 6.15
Q2 = MMBTA05LT1G, ON Semiconductor: Transistor, NPN, 60 V, 0.5 A, AEC-Q101, SOT-23; CompType: BJT; PNP: 0; NPN: 1; Vceo_V: 60; Vcesat1_V: 0.25; IcRated_A: 0.5; TaMin_C: -55; TaMax_C: 150; SizeAreaWB_mm2: 14; SizeArea_mm2: 7.5; SizeX_mm: 2.5; SizeY_mm: 3; SizeZ_mm: 1.1; U/M: EA; AEC Category: Q101; AEC Qualified: Y
Q3 Q7 = CMP-0085314-1: MOSFET, 2-CH, N-CH, 40 V, 40 A, AEC-Q101, SOT1205; Manufacturer: Nexperia; Alternate Manufacturer: None; ChType: N; SizeX_mm: 6.05; Value2: 32.3 nC; AEC Qualified: Y; VdsMax_V: 40V; ChMode: Enhancement; SizeZ_mm: 1.05; Vgs_V: 20V; SizeAreaWB_mm2: 57.35625; Value1: ? ohm; IdsMax_A: 40A; QgTyp_nC: 32.3; Value: 40V; SizeY_mm: 5.125; AEC Category: Q101; SizeArea_mm2: 31.00625
R1 = CRCW040210K0JNED: RES, 10 k, 5%, 0.063 W, 0402; Manufacturer: Vishay-Dale; CompType: Resistor; Value: 10k; Res_ohm: 10000; Value_Code: 10k0; Tolerance_%: 5; Power_W: 0.063; Value2: 0.063W; VDC_V: 50; TempCo: 200 ppm/C; SizeArea_mm2: 0.5; SizeX_mm: 1; SizeZ_mm: 0.6; EIA_Code: E24; U/M: EA; AEC Category: Q200; Green_Lifecycle: Active; Green_REACh: Passed
R2 = CRCW040243K0JNED: RES, 43 k, 5%, 0.063 W, 0402; Manufacturer: Vishay-Dale; CompType: Resistor; Value: 43k; Res_ohm: 43000; Value_Code: 43k0; Tolerance_%: 5; Power_W: 0.063; Value2: 0.063W; VDC_V: 50; TempCo: 200 ppm/C; SizeArea_mm2: 0.5; SizeX_mm: 1; SizeZ_mm: 0.6; EIA_Code: E24; U/M: EA; AEC Category: Q200
R3 R4 R6 R7 = CMP-0025951-3: RES, 100, 1%, 0.063 W, AEC-Q200 Grade 0, 0402; Manufacturer: Vishay-Dale; Power_W: 63mW; TempCo: 100 ppm/C; Value_Code: 100R; Value: 100; EIA_Code: E96; SizeX_mm: 1; SizeY_mm: 0.5; SizeZ_mm: 0.6; Value2: 0.063W; CompType: Resistor; AEC Qualified: Y; VDC_V: 50V; AEC Category: Q200; AEC Grade: 0
R5 = CMP-0026338-2: RES, 3.74 k, 1%, 0.063 W, AEC-Q200 Grade 0, 0402; Manufacturer: Vishay-Dale; Power_W: 63mW; TempCo: 100 ppm/C; Value_Code: 3k74; Value: 3.74k; EIA_Code: E96; SizeX_mm: 1; SizeY_mm: 0.5; SizeZ_mm: 0.6; Value2: 0.063W; CompType: Resistor; AEC Qualified: Y; VDC_V: 50V; AEC Category: Q200; AEC Grade: 0
R8 R11 R16 R25 R26 = CRCW060310K0JNEA: RES, 10 k, 5%, 0.1 W, 0603; Manufacturer: Vishay-Dale; CompType: Resistor; Res_ohm: 10000; Value_Code: 10k0; Tolerance_%: 5; Power_W: 0.1; Value2: 0.1W; VDC_V: 75; TempCo: 200 ppm/C; EIA_Code: E24; U/M: EA; AEC Category: Q200
R9 = CMP-0025785-4: RES, 330, 5%, 0.1 W, AEC-Q200 Grade 0, 0603; Manufacturer: Vishay-Dale; Power_W: 100mW; TempCo: 200 ppm/C; Value_Code: 330R; Value: 330; EIA_Code: E24; SizeX_mm: 1.6; SizeY_mm: 0.8; SizeZ_mm: 1; Value2: 0.1W; SizeArea_mm2: 1.28; CompType: Resistor; AEC Qualified: Y; VDC_V: 75V; AEC Category: Q200; AEC Grade: 0
R10 = CMP-0078669-1: RES, 10.0 k, 1%, 0.063 W, 0402; Manufacturer: Yageo America; Power_W: 63mW; Green_Lifecycle: Active; TempCo: 100 ppm/C; Value_Code: 10k0; Green_REACh: Passed; Value: 10.0k; EIA_Code: E96; Res_ohm: 10k; SizeX_mm: 1; SizeY_mm: 0.5; SizeZ_mm: 0.6; Value2: 0.063W; CompType: Resistor; AEC Qualified: N; AEC Category: Q200
R12 = RC0603JR-07750RL: RES, 750, 5%, 0.1 W, 0603; Manufacturer: Yageo America; CompType: Resistor; Value: 750; Value_Code: 750R; Tolerance_%: 5; Power_W: 0.1; Value2: 0.1W; VDC_V: 50; TempCo: 100 ppm/C; EIA_Code: E24; U/M: EA; AEC Category: Q200
R13 = CMP-0017255-2: RES, 0.003, 1%, 1 W, 1206; Manufacturer: Stackpole Electronics Inc; TempCo: 50 ppm/C; Value_Code: 3L000; U/M: EA; Value: 0.003; EIA_Code: E96; Res_ohm: 3m; SizeX_mm: 3.2; SizeY_mm: 1.6; SizeZ_mm: 1.35; SizeArea_mm2: 5.12; CompType: Resistor; AEC Category: Q200
R14 = CMP-0022109-5: RES, 1.00 k, 1%, 0.1 W, AEC-Q200 Grade 0, 0603; Manufacturer: Vishay-Dale; Power_W: 100mW; TempCo: 100 ppm/C; Value_Code: 1k00; Value: 1.00k; EIA_Code: E96; Res_ohm: 1k; SizeX_mm: 1.6; SizeY_mm: 0.8; SizeZ_mm: 1; Value2: 0.1W; SizeArea_mm2: 1.28; AEC Qualified: Y; VDC_V: 75V; AEC Category: Q200; AEC Grade: 0
R17 = CRCW060310K0FKEA: RES, 10.0 k, 1%, 0.1 W, 0603; Manufacturer: Vishay-Dale; CompType: Resistor; Value: 10.0k; Res_ohm: 10000; Value_Code: 10k0; Tolerance_%: 1; Power_W: 0.1; Value2: 0.1W; VDC_V: 75; TempCo: 100 ppm/C; EIA_Code: E96; U/M: EA; AEC Category: Q200
R22 R23 = CMP-0026224-2: RES, 294, 1%, 0.063 W, AEC-Q200 Grade 0, 0402; Manufacturer: Vishay-Dale; Power_W: 63mW; TempCo: 100 ppm/C; Value_Code: 294R; Value: 294; EIA_Code: E96; SizeX_mm: 1; SizeY_mm: 0.5; SizeZ_mm: 0.6; Value2: 0.063W; AEC Qualified: Y; VDC_V: 50V; AEC Category: Q200; AEC Grade: 0
TB1-TB3 = 1715721: Terminal Block, 5.08 mm, 2x1, TH; Manufacturer: Phoenix Contact; SymbolCreator: a0412235; Pitch_mm: 5.08; Gender: Female; Row_Count: 1; ContactFinish: Tin; Current_A: 17.5; Voltage_V: 400; Cert_CSA: Y; Cert_CULUS: N
TB4 = CMP-0075352-1: Terminal Block, 3.5mm, 3x1, Tin, R/A, TH; Manufacturer: On-Shore Technology; CNHeader: False; Current_A: 10A; Green_Lifecycle: Not Set; Gender: Female; Cert_CSA: Y; Green_REACh: Incomplete; Voltage_V: 125V; Row_Count: 1; Pitch_mm: 3.5; CT: True
TP2 TP5 = 5006: Test Point, Compact, Black, TH; Manufacturer: Keystone; CompType: Test Point Loop; U/M: EA
U1 = CMP-0013312-4: 300mA High-Voltage Ultra-Low-Iq Low-Dropout (LDO) Regulator, DGN0008D (VSSOP-8); Manufacturer: Texas Instruments; SizeX_mm: 5.05; SizeY_mm: 3.1; CompType: IC; SizeZ_mm: 1.1; SizeArea_mm2: 15.655; SizeAreaWB_mm2: 35.955; AEC Category: Q200; AEC Qualified: Y
U2 = CMP-0013806-3: Full-Bridge Automotive Gate Driver, RHB0032E (VQFN-32); Alternate Manufacturer: Texas Instruments; Alternate PartNumber: DRV8703QRHBTQ1; SizeX_mm: 5; CompType: IC; SizeZ_mm: 1; SizeArea_mm2: 25; SizeAreaWB_mm2: 49; U/M: EA
U3 = CMP-0065213-4: Automotive H-Bridge Motor Driver, PWP0024J (TSSOP-24); Manufacturer: Texas Instruments; SizeZ_mm: 1.2; SizeX_mm: 6.4; SizeY_mm: 7.8; SizeArea_mm2: 49.92; CompType: IC; SizeAreaWB_mm2: 82.32; AEC Category: Q200; AEC Qualified: Y
U8 = CMP-0073692-2: 40-V/160-mΩ Dual Channels Smart High-Side Switch, PWP0016J (TSSOP-16); Manufacturer: Texas Instruments; SizeX_mm: 6.4; SizeY_mm: 5.0; CompType: IC; SizeZ_mm: 1.2; SizeArea_mm2: 32.0; SizeAreaWB_mm2: 58.8; U/M: EA; Green_Lifecycle: Active; Green_REACh: Passed

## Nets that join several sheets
3p3V: Power Seat Logic E2 (7 pins), Power Seat Motor Drives E2 (9 pins)
GND: Power Seat Logic E2 (31 pins), Power Seat Motor Drives E2 (42 pins)
VIN+: Power Seat Logic E2 (U5.7 U7.1), Power Seat Motor Drives E2 (25 pins)
DISABLE: Power Seat Logic E2 (J4.10), Power Seat Motor Drives E2 (U3.9)
HSS_FAULT: Power Seat Logic E2 (J4.18), Power Seat Motor Drives E2 (U8.4)
IN1_8703: Power Seat Logic E2 (J5.3), Power Seat Motor Drives E2 (U2.2)
IN1_8873: Power Seat Logic E2 (J5.7), Power Seat Motor Drives E2 (U3.7)
IN2_8703: Power Seat Logic E2 (J5.1), Power Seat Motor Drives E2 (U2.3)
IN2_8873: Power Seat Logic E2 (J5.5), Power Seat Motor Drives E2 (U3.8)
ISense8703: Power Seat Logic E2 (U4.12), Power Seat Motor Drives E2 (C1.1 R5.2 R10.2)
ISense8873: Power Seat Logic E2 (U4.14), Power Seat Motor Drives E2 (C2.1 R17.1)
ISenseHSS: Power Seat Logic E2 (U4.13), Power Seat Motor Drives E2 (R22.1 U8.6)
MODE: Power Seat Logic E2 (J5.9), Power Seat Motor Drives E2 (U2.11)
MOTOR_OUT_1: Power Seat Logic E2 (R20.2), Power Seat Motor Drives E2 (TB2.2 U3.18 U3.19)
nSCS_8703: Power Seat Logic E2 (J5.13), Power Seat Motor Drives E2 (R25.1 U2.5)
nSCS_8873: Power Seat Logic E2 (J4.8), Power Seat Motor Drives E2 (R26.2 U3.6)
nSLEEP: Power Seat Logic E2 (J4.12 U5.2 U7.2), Power Seat Motor Drives E2 (U2.8 U3.11 U8.3)
OK_8703: Power Seat Logic E2 (J4.14), Power Seat Motor Drives E2 (R11.2 U2.10)
OK_8873: Power Seat Logic E2 (J5.8), Power Seat Motor Drives E2 (R16.2 U3.2)
Pump_ON: Power Seat Logic E2 (J4.17), Power Seat Motor Drives E2 (U8.2 U8.5)
SCLK: Power Seat Logic E2 (J4.13), Power Seat Motor Drives E2 (U2.7 U3.5)
SDI: Power Seat Logic E2 (J5.12), Power Seat Motor Drives E2 (U2.6 U3.4)
SDO: Power Seat Logic E2 (J5.14), Power Seat Motor Drives E2 (R12.1 U2.4 U3.3)
SH1: Power Seat Logic E2 (R18.2), Power Seat Motor Drives E2 (7 pins)
Valve_OPEN: Power Seat Logic E2 (J4.15), Power Seat Motor Drives E2 (U8.1)
WDFLT: Power Seat Logic E2 (J5.11), Power Seat Motor Drives E2 (R8.1 U2.9)

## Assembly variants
001: not fitted C9 C10 C15 C16 FID1 FID2 FID3 R3 R4 R7 R8 U7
